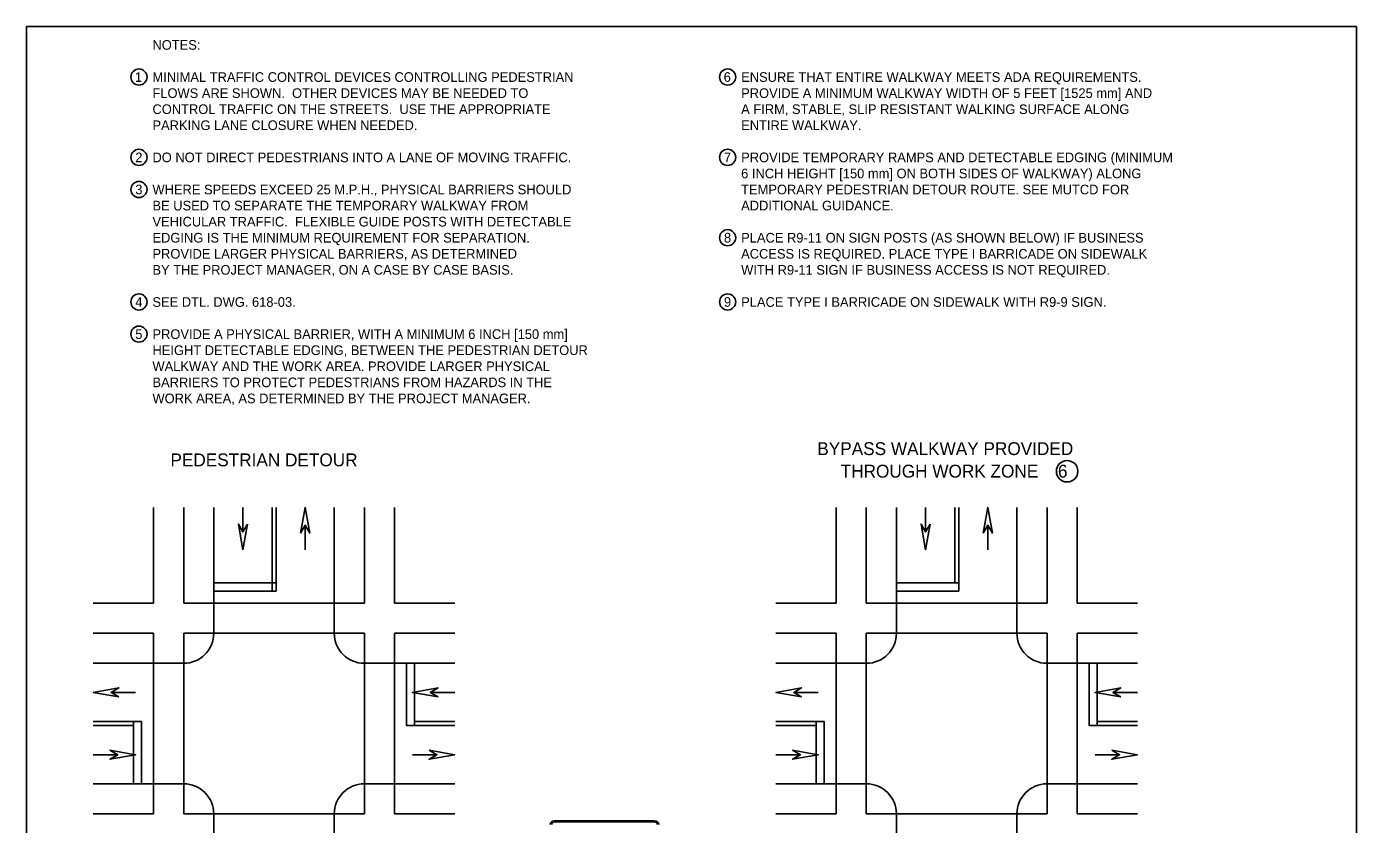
# Model space of a CAD drawing. Extents: x 49991.4 to 50021, y 49987.6 to 50011.4.
# Drawn here: x 50000.34 to 50008.61, y 50006.3 to 50011.26 of the extents above; entities that cross this region are included whole.
import ezdxf

# ---------------------------------------------------------------- set-up
doc = ezdxf.new("R2010")
doc.units = 0
for name, color, linetype in [('Level 1', 7, 'Continuous'), ('Level 2', 7, 'Continuous'), ('Level 3', 7, 'Continuous')]:
    doc.layers.add(name, color=color, linetype=linetype)

msp = doc.modelspace()

# ---------------------------------------------------------------- linework, layer by layer
at = {"layer": 'Level 1'}
for p, q in [((50001.126, 50007.6753), (50001.126, 50008.2704)), ((50001.3135, 50007.6753), (50001.3135, 50008.2704)), ((50001.501, 50007.4878), (50001.501, 50008.2704)), ((50001.6822, 50008.2704), (50001.6822, 50008.1179)), ((50001.6824, 50008.2704), (50001.6824, 50008.1179)), ((50001.8635, 50007.7503), (50001.8635, 50008.2704)), ((50001.8885, 50007.7503), (50001.8885, 50008.2704)), ((50002.251, 50007.4878), (50002.251, 50008.2704)), ((50002.4385, 50007.6753), (50002.4385, 50008.2704)), ((50002.626, 50007.6753), (50002.626, 50008.2704)), ((50005.376, 50007.6753), (50005.376, 50008.2704)), ((50005.5635, 50007.6753), (50005.5635, 50008.2704)), ((50005.751, 50007.4878), (50005.751, 50008.2704)), ((50005.9322, 50008.2704), (50005.9322, 50008.1179)), ((50005.9324, 50008.2704), (50005.9324, 50008.1179)), ((50006.1135, 50007.8003), (50006.1135, 50008.2704)), ((50006.1385, 50007.8003), (50006.1385, 50008.2704)), ((50006.501, 50007.4878), (50006.501, 50008.2704)), ((50006.6885, 50007.6753), (50006.6885, 50008.2704)), ((50006.876, 50007.6753), (50006.876, 50008.2704)), ((50002.0699, 50008.0071), (50002.0699, 50008.1596)), ((50002.0701, 50008.0071), (50002.0701, 50008.1596)), ((50006.3199, 50008.0071), (50006.3199, 50008.1596)), ((50006.3201, 50008.0071), (50006.3201, 50008.1596)), ((50001.126, 50007.6753), (50000.751, 50007.6753)), ((50002.4385, 50007.6753), (50001.3135, 50007.6753)), ((50003.001, 50007.6753), (50002.626, 50007.6753)), ((50005.376, 50007.6753), (50005.001, 50007.6753)), ((50006.6885, 50007.6753), (50005.5635, 50007.6753)), ((50007.251, 50007.6753), (50006.876, 50007.6753)), ((50001.126, 50007.4878), (50000.751, 50007.4878)), ((50001.126, 50006.3628), (50001.126, 50007.4878)), ((50002.4385, 50007.4878), (50001.3135, 50007.4878)), ((50001.3135, 50006.3628), (50001.3135, 50007.4878)), ((50002.4385, 50006.3628), (50002.4385, 50007.4878)), ((50002.626, 50006.3628), (50002.626, 50007.4878)), ((50003.001, 50007.4878), (50002.626, 50007.4878)), ((50005.376, 50007.4878), (50005.001, 50007.4878)), ((50005.376, 50006.3628), (50005.376, 50007.4878)), ((50006.6885, 50007.4878), (50005.5635, 50007.4878)), ((50005.5635, 50006.3628), (50005.5635, 50007.4878)), ((50006.6885, 50006.3628), (50006.6885, 50007.4878)), ((50006.876, 50006.3628), (50006.876, 50007.4878)), ((50007.251, 50007.4878), (50006.876, 50007.4878)), ((50001.3135, 50007.3003), (50000.751, 50007.3003)), ((50003.001, 50007.3003), (50002.4385, 50007.3003)), ((50005.5635, 50007.3003), (50005.001, 50007.3003)), ((50007.251, 50007.3003), (50006.6885, 50007.3003)), ((50001.0143, 50007.1194), (50000.8618, 50007.1194)), ((50001.0143, 50007.1191), (50000.8618, 50007.1191)), ((50003.001, 50007.1192), (50002.8485, 50007.1192)), ((50003.001, 50007.1191), (50002.8485, 50007.1191)), ((50005.2643, 50007.1194), (50005.1118, 50007.1194)), ((50005.2643, 50007.1191), (50005.1118, 50007.1191)), ((50007.251, 50007.1192), (50007.0985, 50007.1192)), ((50007.251, 50007.1191), (50007.0985, 50007.1191)), ((50001.001, 50006.9378), (50000.751, 50006.9378)), ((50001.001, 50006.9128), (50000.751, 50006.9128)), ((50003.001, 50006.9378), (50002.751, 50006.9378)), ((50003.001, 50006.9128), (50002.751, 50006.9128)), ((50005.301, 50006.9378), (50005.001, 50006.9378)), ((50005.251, 50006.9128), (50005.001, 50006.9128)), ((50007.251, 50006.9378), (50007.001, 50006.9378)), ((50007.251, 50006.9128), (50007.001, 50006.9128)), ((50000.751, 50006.7316), (50000.9035, 50006.7316)), ((50000.751, 50006.7315), (50000.9035, 50006.7315)), ((50002.7377, 50006.7316), (50002.8901, 50006.7316)), ((50002.7377, 50006.7313), (50002.8901, 50006.7313)), ((50005.001, 50006.7316), (50005.1535, 50006.7316)), ((50005.001, 50006.7315), (50005.1535, 50006.7315)), ((50006.9877, 50006.7316), (50007.1401, 50006.7316)), ((50006.9877, 50006.7313), (50007.1401, 50006.7313)), ((50001.3135, 50006.5503), (50000.751, 50006.5503)), ((50002.4385, 50006.5503), (50003.001, 50006.5503)), ((50005.5635, 50006.5503), (50005.001, 50006.5503)), ((50006.6885, 50006.5503), (50007.251, 50006.5503)), ((50001.126, 50006.3628), (50000.751, 50006.3628)), ((50002.4385, 50006.3628), (50001.3135, 50006.3628)), ((50001.501, 50003.4852), (50001.501, 50006.3628)), ((50002.251, 50003.4852), (50002.251, 50006.3628)), ((50002.626, 50006.3628), (50003.001, 50006.3628)), ((50003.6227, 50006.3203), (50004.2436, 50006.3203)), ((50005.376, 50006.3628), (50005.001, 50006.3628)), ((50006.6885, 50006.3628), (50005.5635, 50006.3628)), ((50005.751, 50003.4852), (50005.751, 50006.3628)), ((50006.501, 50005.3411), (50006.501, 50006.3628)), ((50006.876, 50006.3628), (50007.251, 50006.3628)), ((50003.6227, 50006.3133), (50004.2436, 50006.3133))]:
    msp.add_line(p, q, dxfattribs=at)
for points in [[(50008.6146, 50011.2628), (50000.3356, 50011.2628), (50000.3356, 50000.0624), (50008.6146, 50000.0624)], [(50002.0418, 50008.1108), (50002.0699, 50008.2704), (50002.0982, 50008.1108), (50002.0699, 50008.1595)], [(50006.2918, 50008.1108), (50006.3199, 50008.2704), (50006.3482, 50008.1108), (50006.3199, 50008.1595)], [(50001.7106, 50008.1667), (50001.6824, 50008.0071), (50001.6541, 50008.1667), (50001.6824, 50008.118)], [(50005.9606, 50008.1667), (50005.9324, 50008.0071), (50005.9041, 50008.1667), (50005.9324, 50008.118)], [(50001.8885, 50007.8003), (50001.8885, 50007.7503), (50001.501, 50007.7503), (50001.501, 50007.8003)], [(50006.1385, 50007.8003), (50006.1385, 50007.7503), (50005.751, 50007.7503), (50005.751, 50007.8003)], [(50002.751, 50006.9128), (50002.701, 50006.9128), (50002.701, 50007.3003), (50002.751, 50007.3003)], [(50007.001, 50006.9128), (50006.951, 50006.9128), (50006.951, 50007.3003), (50007.001, 50007.3003)], [(50000.9106, 50007.091), (50000.751, 50007.1191), (50000.9106, 50007.1474), (50000.8619, 50007.1191)], [(50002.8973, 50007.0909), (50002.7377, 50007.1191), (50002.8973, 50007.1473), (50002.8486, 50007.1191)], [(50005.1606, 50007.091), (50005.001, 50007.1191), (50005.1606, 50007.1474), (50005.1119, 50007.1191)], [(50007.1473, 50007.0909), (50006.9877, 50007.1191), (50007.1473, 50007.1473), (50007.0986, 50007.1191)], [(50001.001, 50006.9378), (50001.051, 50006.9378), (50001.051, 50006.5503), (50001.001, 50006.5503)], [(50005.251, 50006.9378), (50005.301, 50006.9378), (50005.301, 50006.5503), (50005.251, 50006.5503)], [(50000.8547, 50006.7598), (50001.0143, 50006.7316), (50000.8547, 50006.7034), (50000.9034, 50006.7316)], [(50002.8413, 50006.7597), (50003.001, 50006.7316), (50002.8413, 50006.7032), (50002.8901, 50006.7316)], [(50005.1047, 50006.7598), (50005.2643, 50006.7316), (50005.1047, 50006.7034), (50005.1534, 50006.7316)], [(50007.0913, 50006.7597), (50007.251, 50006.7316), (50007.0913, 50006.7032), (50007.1401, 50006.7316)]]:
    msp.add_lwpolyline(points, close=True, dxfattribs=at)
for centre, start, end in [((50001.3135, 50007.4878), 270, 0), ((50002.4385, 50007.4878), 180, 270), ((50005.5635, 50007.4878), 270, 0), ((50006.6885, 50007.4878), 180, 270), ((50001.3135, 50006.3628), 0, 90), ((50002.4385, 50006.3628), 90, 180), ((50005.5635, 50006.3628), 0, 90), ((50006.6885, 50006.3628), 90, 180)]:
    msp.add_arc(centre, 0.1875, start, end, dxfattribs=at)
for centre, major_axis, start_param, end_param in [((50003.6227, 50006.2979), (-0.0282, 0), 4.712389, 6.283185), ((50004.2436, 50006.2979), (0.0282, 0), 0, 1.570796), ((50003.6227, 50006.2979), (-0.0194, 0), 4.712389, 6.283185), ((50004.2436, 50006.2979), (0.0194, 0), 0, 1.570796)]:
    msp.add_ellipse(centre, major_axis=major_axis, ratio=0.794444, start_param=start_param, end_param=end_param, dxfattribs=at)
at = {"layer": 'Level 2'}
for centre, radius in [((50001.0351, 50010.949), 0.0501), ((50004.7001, 50010.9491), 0.0501), ((50001.0351, 50010.449), 0.0501), ((50004.7001, 50010.4491), 0.0501), ((50001.0351, 50010.249), 0.0501), ((50004.7001, 50009.9491), 0.0501), ((50001.0351, 50009.549), 0.0501), ((50004.7001, 50009.5491), 0.0501), ((50001.0351, 50009.3491), 0.0501), ((50006.8138, 50008.4956), 0.0668)]:
    msp.add_circle(centre, radius, dxfattribs=at)
at = {"layer": 'Level 3'}
for p, q in [((50008.6146, 50010.4061), (50008.6146, 50009.0084)), ((50000.3356, 50010.2638), (50000.3356, 50008.8984))]:
    msp.add_line(p, q, dxfattribs=at)

# ---------------------------------------------------------------- texts
at = {"layer": 'Level 2'}
for s, height, p in [('NOTES:', 0.06, (50001.1192, 50011.1189)), ('1', 0.06, (50001.0099, 50010.919)), ('MINIMAL TRAFFIC CONTROL DEVICES CONTROLLING PEDESTRIAN', 0.06, (50001.1192, 50010.9189)), ('6', 0.06, (50004.6756, 50010.9191)), ('ENSURE THAT ENTIRE WALKWAY MEETS ADA REQUIREMENTS.  ', 0.06, (50004.7842, 50010.9189)), ('FLOWS ARE SHOWN.  OTHER DEVICES MAY BE NEEDED TO ', 0.06, (50001.1192, 50010.8189)), ('PROVIDE A MINIMUM WALKWAY WIDTH OF 5 FEET [1525 mm] AND', 0.06, (50004.7842, 50010.8189)), ('CONTROL TRAFFIC ON THE STREETS.  USE THE APPROPRIATE', 0.06, (50001.1192, 50010.7189)), ('A FIRM, STABLE, SLIP RESISTANT WALKING SURFACE ALONG ', 0.06, (50004.7842, 50010.7189)), ('PARKING LANE CLOSURE WHEN NEEDED.', 0.06, (50001.1192, 50010.6189)), ('ENTIRE WALKWAY.', 0.06, (50004.7842, 50010.6189)), ('2', 0.06, (50001.0123, 50010.419)), ('DO NOT DIRECT PEDESTRIANS INTO A LANE OF MOVING TRAFFIC.', 0.06, (50001.1192, 50010.4189)), ('7', 0.06, (50004.6773, 50010.4191)), ('PROVIDE TEMPORARY RAMPS AND DETECTABLE EDGING (MINIMUM', 0.06, (50004.7842, 50010.4189)), ('6 INCH HEIGHT [150 mm] ON BOTH SIDES OF WALKWAY) ALONG ', 0.06, (50004.7842, 50010.3189)), ('3', 0.06, (50001.0123, 50010.219)), ('WHERE SPEEDS EXCEED 25 M.P.H., PHYSICAL BARRIERS SHOULD', 0.06, (50001.1192, 50010.2189)), ('TEMPORARY PEDESTRIAN DETOUR ROUTE. SEE MUTCD FOR ', 0.06, (50004.7842, 50010.2189)), ('BE USED TO SEPARATE THE TEMPORARY WALKWAY FROM', 0.06, (50001.1192, 50010.1189)), ('ADDITIONAL GUIDANCE.', 0.06, (50004.7842, 50010.1189)), ('VEHICULAR TRAFFIC.  FLEXIBLE GUIDE POSTS WITH DETECTABLE', 0.06, (50001.1192, 50010.0189)), ('EDGING IS THE MINIMUM REQUIREMENT FOR SEPARATION.', 0.06, (50001.1192, 50009.9189)), ('8', 0.06, (50004.6773, 50009.9191)), ('PLACE R9-11 ON SIGN POSTS (AS SHOWN BELOW) IF BUSINESS', 0.06, (50004.7842, 50009.9189)), ('PROVIDE LARGER PHYSICAL BARRIERS, AS DETERMINED ', 0.06, (50001.1192, 50009.8189)), ('ACCESS IS REQUIRED. PLACE TYPE I BARRICADE ON SIDEWALK', 0.06, (50004.7842, 50009.8189)), ('BY THE PROJECT MANAGER, ON A CASE BY CASE BASIS.', 0.06, (50001.1192, 50009.7189)), ('WITH R9-11 SIGN IF BUSINESS ACCESS IS NOT REQUIRED.', 0.06, (50004.7842, 50009.7189)), ('4', 0.06, (50001.0123, 50009.519)), ('SEE DTL. DWG. 618-03.', 0.06, (50001.1192, 50009.5189)), ('9', 0.06, (50004.677, 50009.5191)), ('PLACE TYPE I BARRICADE ON SIDEWALK WITH R9-9 SIGN.', 0.06, (50004.7842, 50009.5189)), ('5', 0.06, (50001.0123, 50009.3191)), ('PROVIDE A PHYSICAL BARRIER, WITH A MINIMUM 6 INCH [150 mm]', 0.06, (50001.1192, 50009.3189)), ('HEIGHT DETECTABLE EDGING, BETWEEN THE PEDESTRIAN DETOUR', 0.06, (50001.1192, 50009.2189)), ('WALKWAY AND THE WORK AREA. PROVIDE LARGER PHYSICAL', 0.06, (50001.1192, 50009.1189)), ('BARRIERS TO PROTECT PEDESTRIANS FROM HAZARDS IN THE', 0.06, (50001.1192, 50009.0189)), ('WORK AREA, AS DETERMINED BY THE PROJECT MANAGER.', 0.06, (50001.1192, 50008.9189)), ('BYPASS WALKWAY PROVIDED', 0.08, (50005.2585, 50008.5963)), ('PEDESTRIAN DETOUR', 0.08, (50001.2311, 50008.5263)), ('THROUGH WORK ZONE', 0.08, (50005.4038, 50008.4563)), (' 6', 0.08, (50006.7267, 50008.4563))]:
    msp.add_text(s, height=height, dxfattribs=at).set_placement(p)

doc.saveas('drawing.dxf')
